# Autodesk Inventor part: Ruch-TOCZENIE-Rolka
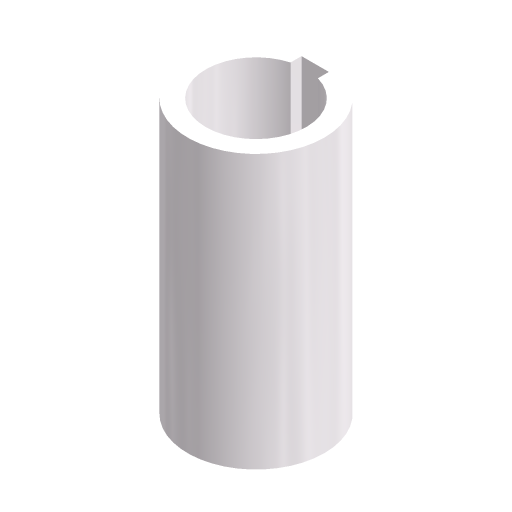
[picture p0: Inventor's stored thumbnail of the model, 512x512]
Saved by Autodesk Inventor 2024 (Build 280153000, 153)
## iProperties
Company: ATC
Created: 2023-03
Part Number: Ruch-TOCZENIE-Rolka
Document SubType Name: Modeling
Designer: Andrzej Jaskulski
Manufacturer: Standard
Standards Organization: Custom
Material: Kurs-AJ
Stock Number: Ruch-TOCZENIE-Rolka
Density: 1 g/cm^3
Appearance: Kurs-AJ
Checked By: A.J.
Engr Approved By: Andrzej Jaskulski
Mfg Approved By: Andrzej Jaskulski
Authority: A.J.
DE: 15,000 mm
Title: A.J.: Kurs R2024-MEP
Author: Andrzej Jaskulski
Revision Number: 1/24
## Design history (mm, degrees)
sketch "Szkic1"
  geometry: C1 r 7.5 at (-49.399, 1.842)
  constraints: 1 centre point
  dimensions: "DE" = 15 diameter of C1
extrude "Wyciągnięcie proste1" new body sketch "Szkic1" distance "d0" = 30; taper "d1" = 0 deg
node "Oś"
sketch "Sketch3"
  geometry: L1 (0, 0.215)-(0, 7.5); L2 (-1.5, 6.5)-(1.5, 6.5); L3 (1.5, 6.5)-(1.5, 5.292); L4 (-1.5, 5.292)-(-1.5, 6.5); A1 r 5.5 centre (0, 0) between (-1.5, 5.292) and (1.5, 5.292); 2 further points
  constraints: 8 end point, 2 point on circle, 2 vertical alignment, 1 centre point, 1 coincident, 1 horizontal, 1 midpoint, 1 parallel, 1 perpendicular, 1 vertical, 1 other
  dimensions: "d4" = 3 distance of L2.start L2.end; "d6" = 11 diameter of A1; "d7" = 6.5 distance from line of point (0, 0) L2
extrude "Extrusion3" cut sketch "Sketch3" extent not by distance; stored distance "d8" = 10; taper "d9" = 0 deg
node "Bryła1"
node "Korpusy bryłowe"
node "Korpusy powierzchniowe"
